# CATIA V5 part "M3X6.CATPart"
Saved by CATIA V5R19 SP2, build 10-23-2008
Part number: M3X6
Definition: design
Nomenclature: M3X6
Source: Unknown
Bounding box of the stored display mesh (mm): x -3.002 to 3.002, y -3.002 to 3.002, z 0 to 6
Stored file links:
  Z:\fausse table rondelle-20220905T211342Z-001\fausse table rondelle\M3X6.CATPart
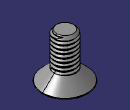
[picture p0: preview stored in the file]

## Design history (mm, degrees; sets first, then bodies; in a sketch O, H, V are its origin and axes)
AxisSystem1: origin (0, 0, 0), X (1, 0, 0), Y (0, 1, 0), Z (0, 0, 1)
Set1
  DatumSurface1 "OPEN_SHELL #245692"
Body1 (main body)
